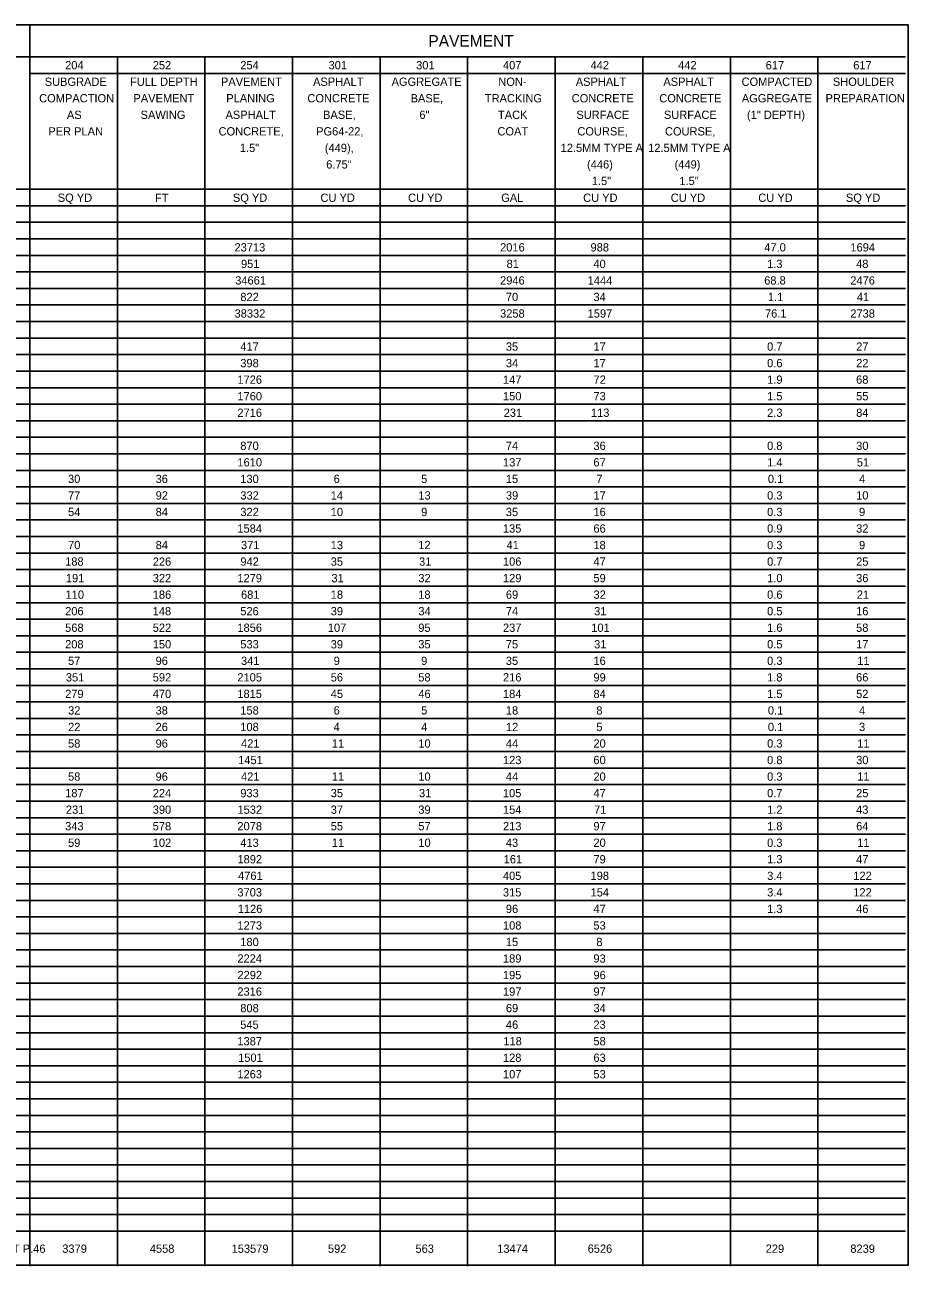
# Model space of a CAD drawing. Extents: x 12522 to 13018, y 1124 to 1902.
# Drawn here: x 12812.77 to 12827.72, y 1804.63 to 1825.65 of the extents above; entities that cross this region are included whole.
import ezdxf

# ---------------------------------------------------------------- set-up
doc = ezdxf.new("R2010")
doc.units = 0
for name, color, linetype in [('SC_Scratch1', 7, 'Continuous'), ('SH_Data', 7, 'Continuous'), ('SH_Text', 7, 'Continuous')]:
    doc.layers.add(name, color=color, linetype=linetype)

msp = doc.modelspace()

# ---------------------------------------------------------------- linework, layer by layer
at = {"layer": 'SC_Scratch1'}
msp.add_lwpolyline([(12797.224, 1825.65), (12827.724, 1825.65), (12827.724, 1804.65), (12797.224, 1804.65)], close=True, dxfattribs=at)
at = {"layer": 'SH_Data'}
for p, q in [((12812.855, 1825.65), (12812.855, 1804.634)), ((12797.224, 1825.107), (12827.678, 1825.107)), ((12814.337, 1825.107), (12814.337, 1804.634)), ((12815.82, 1825.107), (12815.82, 1804.634)), ((12817.302, 1825.107), (12817.302, 1804.634)), ((12818.784, 1825.107), (12818.784, 1804.634)), ((12820.267, 1825.107), (12820.267, 1804.634)), ((12821.749, 1825.107), (12821.749, 1804.634)), ((12823.231, 1825.107), (12823.231, 1804.634)), ((12824.714, 1825.107), (12824.714, 1804.634)), ((12826.196, 1825.107), (12826.196, 1804.634)), ((12812.855, 1824.827), (12827.678, 1824.827)), ((12806.184, 1822.867), (12827.678, 1822.867)), ((12797.224, 1822.587), (12827.678, 1822.587)), ((12797.224, 1822.307), (12827.678, 1822.307)), ((12797.224, 1822.027), (12827.678, 1822.027)), ((12797.224, 1821.747), (12827.678, 1821.747)), ((12797.224, 1821.467), (12827.678, 1821.467)), ((12797.224, 1821.187), (12827.678, 1821.187)), ((12797.224, 1820.907), (12827.678, 1820.907)), ((12797.224, 1820.627), (12827.678, 1820.627)), ((12797.224, 1820.347), (12827.678, 1820.347)), ((12797.224, 1820.067), (12827.678, 1820.067)), ((12797.224, 1819.787), (12827.678, 1819.787)), ((12797.224, 1819.507), (12827.678, 1819.507)), ((12797.224, 1819.227), (12827.678, 1819.227)), ((12797.224, 1818.947), (12827.678, 1818.947)), ((12797.224, 1818.667), (12827.678, 1818.667)), ((12797.224, 1818.387), (12827.678, 1818.387)), ((12797.224, 1818.107), (12827.678, 1818.107)), ((12797.224, 1817.827), (12827.678, 1817.827)), ((12797.224, 1817.547), (12827.678, 1817.547)), ((12797.224, 1817.267), (12827.678, 1817.267)), ((12797.224, 1816.987), (12827.678, 1816.987)), ((12797.224, 1816.707), (12827.678, 1816.707)), ((12797.224, 1816.427), (12827.678, 1816.427)), ((12797.224, 1816.147), (12827.678, 1816.147)), ((12797.224, 1815.867), (12827.678, 1815.867)), ((12797.224, 1815.587), (12827.678, 1815.587)), ((12797.224, 1815.307), (12827.678, 1815.307)), ((12797.224, 1815.027), (12827.678, 1815.027)), ((12797.224, 1814.747), (12827.678, 1814.747)), ((12797.224, 1814.467), (12827.678, 1814.467)), ((12797.224, 1814.187), (12827.678, 1814.187)), ((12797.224, 1813.907), (12827.678, 1813.907)), ((12797.224, 1813.627), (12827.678, 1813.627)), ((12797.224, 1813.347), (12827.678, 1813.347)), ((12797.224, 1813.067), (12827.678, 1813.067)), ((12797.224, 1812.787), (12827.678, 1812.787)), ((12797.224, 1812.507), (12827.678, 1812.507)), ((12797.224, 1812.227), (12827.678, 1812.227)), ((12797.224, 1811.947), (12827.678, 1811.947)), ((12797.224, 1811.667), (12827.678, 1811.667)), ((12797.224, 1811.387), (12827.678, 1811.387)), ((12797.224, 1811.107), (12827.678, 1811.107)), ((12797.224, 1810.827), (12827.678, 1810.827)), ((12797.224, 1810.547), (12827.678, 1810.547)), ((12797.224, 1810.267), (12827.678, 1810.267)), ((12797.224, 1809.987), (12827.678, 1809.987)), ((12797.224, 1809.707), (12827.678, 1809.707)), ((12797.224, 1809.427), (12827.678, 1809.427)), ((12797.224, 1809.147), (12827.678, 1809.147)), ((12797.224, 1808.867), (12827.678, 1808.867)), ((12797.224, 1808.587), (12827.678, 1808.587)), ((12797.224, 1808.307), (12827.678, 1808.307)), ((12797.224, 1808.027), (12827.678, 1808.027)), ((12797.224, 1807.747), (12827.678, 1807.747)), ((12797.224, 1807.467), (12827.678, 1807.467)), ((12797.224, 1807.187), (12827.678, 1807.187)), ((12797.224, 1806.907), (12827.678, 1806.907)), ((12797.224, 1806.627), (12827.678, 1806.627)), ((12797.224, 1806.347), (12827.678, 1806.347)), ((12797.224, 1806.067), (12827.678, 1806.067)), ((12797.224, 1805.787), (12827.678, 1805.787)), ((12797.224, 1805.507), (12827.678, 1805.507)), ((12797.224, 1805.227), (12827.678, 1805.227))]:
    msp.add_line(p, q, dxfattribs=at)

# ---------------------------------------------------------------- texts
at = {"layer": 'SH_Text'}
for s, height, p in [('PAVEMENT', 0.196, (12819.603, 1825.28)), ('204', 0.14, (12813.453, 1824.897)), ('252', 0.14, (12814.936, 1824.897)), ('254', 0.14, (12816.418, 1824.897)), ('301', 0.14, (12817.912, 1824.897)), ('301', 0.14, (12819.395, 1824.897)), ('407', 0.14, (12820.865, 1824.897)), ('442', 0.14, (12822.348, 1824.897)), ('442', 0.14, (12823.83, 1824.897)), ('617', 0.14, (12825.312, 1824.897)), ('617', 0.14, (12826.794, 1824.897)), ('SUBGRADE', 0.14, (12813.107, 1824.617)), ('FULL DEPTH', 0.14, (12814.551, 1824.617)), ('PAVEMENT', 0.14, (12816.091, 1824.617)), ('ASPHALT', 0.14, (12817.65, 1824.617)), ('AGGREGATE', 0.14, (12818.979, 1824.617)), ('NON-', 0.14, (12820.786, 1824.617)), ('ASPHALT', 0.14, (12822.097, 1824.617)), ('ASPHALT', 0.14, (12823.58, 1824.617)), ('COMPACTED', 0.14, (12824.904, 1824.617)), ('SHOULDER', 0.14, (12826.449, 1824.617)), ('COMPACTION', 0.14, (12813.013, 1824.337)), ('PAVEMENT', 0.14, (12814.609, 1824.337)), ('PLANING', 0.14, (12816.18, 1824.337)), ('CONCRETE', 0.14, (12817.554, 1824.337)), (' BASE,', 0.14, (12819.249, 1824.337)), ('TRACKING', 0.14, (12820.558, 1824.337)), (' CONCRETE', 0.14, (12821.976, 1824.337)), (' CONCRETE', 0.14, (12823.459, 1824.337)), ('AGGREGATE', 0.14, (12824.908, 1824.337)), ('PREPARATION', 0.14, (12826.326, 1824.337)), ('AS', 0.14, (12813.483, 1824.057)), ('SAWING', 0.14, (12814.73, 1824.057)), ('ASPHALT', 0.14, (12816.168, 1824.057)), (' BASE,', 0.14, (12817.767, 1824.057)), ('6"', 0.14, (12819.449, 1824.057)), ('TACK', 0.14, (12820.78, 1824.057)), (' SURFACE', 0.14, (12822.055, 1824.057)), (' SURFACE', 0.14, (12823.537, 1824.057)), ('(1" DEPTH)', 0.14, (12824.996, 1824.057)), ('PER PLAN', 0.14, (12813.168, 1823.777)), ('CONCRETE,', 0.14, (12816.05, 1823.777)), (' PG64-22,', 0.14, (12817.65, 1823.777)), ('COAT', 0.14, (12820.771, 1823.777)), (' COURSE,', 0.14, (12822.072, 1823.777)), (' COURSE,', 0.14, (12823.555, 1823.777)), ('1.5"', 0.14, (12816.411, 1823.497)), (' (449),', 0.14, (12817.797, 1823.497)), ('12.5MM TYPE A', 0.14, (12821.841, 1823.497)), ('12.5MM TYPE A', 0.14, (12823.323, 1823.497)), (' 6.75"', 0.14, (12817.82, 1823.217)), ('(446)', 0.14, (12822.288, 1823.217)), ('(449)', 0.14, (12823.77, 1823.217)), (' 1.5"', 0.14, (12822.316, 1822.937)), (' 1.5"', 0.14, (12823.799, 1822.937)), ('SQ YD', 0.14, (12813.328, 1822.653)), ('FT', 0.14, (12814.973, 1822.653)), ('SQ YD', 0.14, (12816.293, 1822.653)), ('CU YD', 0.14, (12817.775, 1822.653)), ('CU YD', 0.14, (12819.258, 1822.653)), ('GAL', 0.14, (12820.835, 1822.653)), ('CU YD', 0.14, (12822.222, 1822.653)), ('CU YD', 0.14, (12823.705, 1822.653)), ('CU YD', 0.14, (12825.187, 1822.653)), ('SQ YD', 0.14, (12826.67, 1822.653)), ('23713', 0.14, (12816.32, 1821.813)), ('2016', 0.14, (12820.816, 1821.813)), ('988', 0.14, (12822.347, 1821.813)), ('47.0', 0.14, (12825.288, 1821.813)), ('1694', 0.14, (12826.746, 1821.813)), ('951', 0.14, (12816.43, 1821.533)), ('81', 0.14, (12820.926, 1821.533)), ('40', 0.14, (12822.396, 1821.533)), ('1.3', 0.14, (12825.336, 1821.533)), ('48', 0.14, (12826.843, 1821.533)), ('34661', 0.14, (12816.332, 1821.253)), ('2946', 0.14, (12820.816, 1821.253)), ('1444', 0.14, (12822.299, 1821.253)), ('68.8', 0.14, (12825.287, 1821.253)), ('2476', 0.14, (12826.745, 1821.253)), ('822', 0.14, (12816.419, 1820.973)), ('70', 0.14, (12820.914, 1820.973)), ('34', 0.14, (12822.397, 1820.973)), ('1.1', 0.14, (12825.349, 1820.973)), ('41', 0.14, (12826.855, 1820.973)), ('38332', 0.14, (12816.321, 1820.693)), ('3258', 0.14, (12820.816, 1820.693)), ('1597', 0.14, (12822.298, 1820.693)), ('76.1', 0.14, (12825.3, 1820.693)), ('2738', 0.14, (12826.745, 1820.693)), ('417', 0.14, (12816.418, 1820.133)), ('35', 0.14, (12820.913, 1820.133)), ('17', 0.14, (12822.396, 1820.133)), ('0.7', 0.14, (12825.336, 1820.133)), ('27', 0.14, (12826.843, 1820.133)), ('398', 0.14, (12816.418, 1819.853)), ('34', 0.14, (12820.914, 1819.853)), ('17', 0.14, (12822.396, 1819.853)), ('0.6', 0.14, (12825.336, 1819.853)), ('22', 0.14, (12826.844, 1819.853)), ('1726', 0.14, (12816.369, 1819.573)), ('147', 0.14, (12820.865, 1819.573)), ('72', 0.14, (12822.397, 1819.573)), ('1.9', 0.14, (12825.336, 1819.573)), ('68', 0.14, (12826.843, 1819.573)), ('1760', 0.14, (12816.369, 1819.293)), ('150', 0.14, (12820.865, 1819.293)), ('73', 0.14, (12822.396, 1819.293)), ('1.5', 0.14, (12825.336, 1819.293)), ('55', 0.14, (12826.843, 1819.293)), ('2716', 0.14, (12816.369, 1819.013)), ('231', 0.14, (12820.877, 1819.013)), ('113', 0.14, (12822.354, 1819.013)), ('2.3', 0.14, (12825.336, 1819.013)), ('84', 0.14, (12826.844, 1819.013)), ('870', 0.14, (12816.418, 1818.453)), ('74', 0.14, (12820.914, 1818.453)), ('36', 0.14, (12822.396, 1818.453)), ('0.8', 0.14, (12825.336, 1818.453)), ('30', 0.14, (12826.844, 1818.453)), ('1610', 0.14, (12816.369, 1818.173)), ('137', 0.14, (12820.865, 1818.173)), ('67', 0.14, (12822.396, 1818.173)), ('1.4', 0.14, (12825.337, 1818.173)), ('51', 0.14, (12826.855, 1818.173)), ('30', 0.14, (12813.502, 1817.893)), ('36', 0.14, (12814.984, 1817.893)), ('130', 0.14, (12816.418, 1817.893)), ('6', 0.14, (12817.998, 1817.893)), ('5', 0.14, (12819.48, 1817.893)), ('15', 0.14, (12820.913, 1817.893)), ('7', 0.14, (12822.445, 1817.893)), ('0.1', 0.14, (12825.349, 1817.893)), ('4', 0.14, (12826.893, 1817.893)), ('77', 0.14, (12813.502, 1817.613)), ('92', 0.14, (12814.985, 1817.613)), ('332', 0.14, (12816.419, 1817.613)), ('14', 0.14, (12817.949, 1817.613)), ('13', 0.14, (12819.432, 1817.613)), ('39', 0.14, (12820.914, 1817.613)), ('17', 0.14, (12822.396, 1817.613)), ('0.3', 0.14, (12825.336, 1817.613)), ('10', 0.14, (12826.844, 1817.613)), ('54', 0.14, (12813.502, 1817.333)), ('84', 0.14, (12814.985, 1817.333)), ('322', 0.14, (12816.419, 1817.333)), ('10', 0.14, (12817.949, 1817.333)), ('9', 0.14, (12819.48, 1817.333)), ('35', 0.14, (12820.913, 1817.333)), ('16', 0.14, (12822.396, 1817.333)), ('0.3', 0.14, (12825.336, 1817.333)), ('9', 0.14, (12826.892, 1817.333)), ('1584', 0.14, (12816.369, 1817.053)), ('135', 0.14, (12820.864, 1817.053)), ('66', 0.14, (12822.396, 1817.053)), ('0.9', 0.14, (12825.336, 1817.053)), ('32', 0.14, (12826.844, 1817.053)), ('70', 0.14, (12813.502, 1816.773)), ('84', 0.14, (12814.985, 1816.773)), ('371', 0.14, (12816.43, 1816.773)), ('13', 0.14, (12817.949, 1816.773)), ('12', 0.14, (12819.432, 1816.773)), ('41', 0.14, (12820.926, 1816.773)), ('18', 0.14, (12822.396, 1816.773)), ('0.3', 0.14, (12825.336, 1816.773)), ('9', 0.14, (12826.892, 1816.773)), ('188', 0.14, (12813.453, 1816.493)), ('226', 0.14, (12814.936, 1816.493)), ('942', 0.14, (12816.419, 1816.493)), ('35', 0.14, (12817.949, 1816.493)), ('31', 0.14, (12819.444, 1816.493)), ('106', 0.14, (12820.865, 1816.493)), ('47', 0.14, (12822.396, 1816.493)), ('0.7', 0.14, (12825.336, 1816.493)), ('25', 0.14, (12826.843, 1816.493)), ('191', 0.14, (12813.465, 1816.213)), ('322', 0.14, (12814.936, 1816.213)), ('1279', 0.14, (12816.369, 1816.213)), ('31', 0.14, (12817.961, 1816.213)), ('32', 0.14, (12819.432, 1816.213)), ('129', 0.14, (12820.865, 1816.213)), ('59', 0.14, (12822.396, 1816.213)), ('1.0', 0.14, (12825.337, 1816.213)), ('36', 0.14, (12826.843, 1816.213)), ('110', 0.14, (12813.46, 1815.933)), ('186', 0.14, (12814.936, 1815.933)), ('681', 0.14, (12816.43, 1815.933)), ('18', 0.14, (12817.949, 1815.933)), ('18', 0.14, (12819.431, 1815.933)), ('69', 0.14, (12820.914, 1815.933)), ('32', 0.14, (12822.397, 1815.933)), ('0.6', 0.14, (12825.336, 1815.933)), ('21', 0.14, (12826.855, 1815.933)), ('206', 0.14, (12813.453, 1815.653)), ('148', 0.14, (12814.935, 1815.653)), ('526', 0.14, (12816.418, 1815.653)), ('39', 0.14, (12817.949, 1815.653)), ('34', 0.14, (12819.432, 1815.653)), ('74', 0.14, (12820.914, 1815.653)), ('31', 0.14, (12822.408, 1815.653)), ('0.5', 0.14, (12825.336, 1815.653)), ('16', 0.14, (12826.843, 1815.653)), ('568', 0.14, (12813.453, 1815.373)), ('522', 0.14, (12814.936, 1815.373)), ('1856', 0.14, (12816.369, 1815.373)), ('107', 0.14, (12817.9, 1815.373)), ('95', 0.14, (12819.431, 1815.373)), ('237', 0.14, (12820.865, 1815.373)), ('101', 0.14, (12822.359, 1815.373)), ('1.6', 0.14, (12825.336, 1815.373)), ('58', 0.14, (12826.843, 1815.373)), ('208', 0.14, (12813.453, 1815.093)), ('150', 0.14, (12814.936, 1815.093)), ('533', 0.14, (12816.418, 1815.093)), ('39', 0.14, (12817.949, 1815.093)), ('35', 0.14, (12819.431, 1815.093)), ('75', 0.14, (12820.913, 1815.093)), ('31', 0.14, (12822.408, 1815.093)), ('0.5', 0.14, (12825.336, 1815.093)), ('17', 0.14, (12826.843, 1815.093)), ('57', 0.14, (12813.502, 1814.813)), ('96', 0.14, (12814.984, 1814.813)), ('341', 0.14, (12816.43, 1814.813)), ('9', 0.14, (12817.998, 1814.813)), ('9', 0.14, (12819.48, 1814.813)), ('35', 0.14, (12820.913, 1814.813)), ('16', 0.14, (12822.396, 1814.813)), ('0.3', 0.14, (12825.336, 1814.813)), ('11', 0.14, (12826.862, 1814.813)), ('351', 0.14, (12813.465, 1814.533)), ('592', 0.14, (12814.936, 1814.533)), ('2105', 0.14, (12816.368, 1814.533)), ('56', 0.14, (12817.949, 1814.533)), ('58', 0.14, (12819.431, 1814.533)), ('216', 0.14, (12820.865, 1814.533)), ('99', 0.14, (12822.396, 1814.533)), ('1.8', 0.14, (12825.336, 1814.533)), ('66', 0.14, (12826.843, 1814.533)), ('279', 0.14, (12813.453, 1814.253)), ('470', 0.14, (12814.936, 1814.253)), ('1815', 0.14, (12816.368, 1814.253)), ('45', 0.14, (12817.949, 1814.253)), ('46', 0.14, (12819.432, 1814.253)), ('184', 0.14, (12820.865, 1814.253)), ('84', 0.14, (12822.397, 1814.253)), ('1.5', 0.14, (12825.336, 1814.253)), ('52', 0.14, (12826.844, 1814.253)), ('32', 0.14, (12813.503, 1813.973)), ('38', 0.14, (12814.984, 1813.973)), ('158', 0.14, (12816.418, 1813.973)), ('6', 0.14, (12817.998, 1813.973)), ('5', 0.14, (12819.48, 1813.973)), ('18', 0.14, (12820.914, 1813.973)), ('8', 0.14, (12822.445, 1813.973)), ('0.1', 0.14, (12825.349, 1813.973)), ('4', 0.14, (12826.893, 1813.973)), ('22', 0.14, (12813.503, 1813.693)), ('26', 0.14, (12814.984, 1813.693)), ('108', 0.14, (12816.418, 1813.693)), ('4', 0.14, (12817.998, 1813.693)), ('4', 0.14, (12819.481, 1813.693)), ('12', 0.14, (12820.915, 1813.693)), ('5', 0.14, (12822.445, 1813.693)), ('0.1', 0.14, (12825.349, 1813.693)), ('3', 0.14, (12826.892, 1813.693)), ('58', 0.14, (12813.502, 1813.413)), ('96', 0.14, (12814.984, 1813.413)), ('421', 0.14, (12816.43, 1813.413)), ('11', 0.14, (12817.968, 1813.413)), ('10', 0.14, (12819.432, 1813.413)), ('44', 0.14, (12820.914, 1813.413)), ('20', 0.14, (12822.396, 1813.413)), ('0.3', 0.14, (12825.336, 1813.413)), ('11', 0.14, (12826.862, 1813.413)), ('1451', 0.14, (12816.381, 1813.133)), ('123', 0.14, (12820.865, 1813.133)), ('60', 0.14, (12822.396, 1813.133)), ('0.8', 0.14, (12825.336, 1813.133)), ('30', 0.14, (12826.844, 1813.133)), ('58', 0.14, (12813.502, 1812.853)), ('96', 0.14, (12814.984, 1812.853)), ('421', 0.14, (12816.43, 1812.853)), ('11', 0.14, (12817.968, 1812.853)), ('10', 0.14, (12819.432, 1812.853)), ('44', 0.14, (12820.914, 1812.853)), ('20', 0.14, (12822.396, 1812.853)), ('0.3', 0.14, (12825.336, 1812.853)), ('11', 0.14, (12826.862, 1812.853)), ('187', 0.14, (12813.453, 1812.573)), ('224', 0.14, (12814.936, 1812.573)), ('933', 0.14, (12816.418, 1812.573)), ('35', 0.14, (12817.949, 1812.573)), ('31', 0.14, (12819.444, 1812.573)), ('105', 0.14, (12820.864, 1812.573)), ('47', 0.14, (12822.396, 1812.573)), ('0.7', 0.14, (12825.336, 1812.573)), ('25', 0.14, (12826.843, 1812.573)), ('231', 0.14, (12813.465, 1812.293)), ('390', 0.14, (12814.936, 1812.293)), ('1532', 0.14, (12816.37, 1812.293)), ('37', 0.14, (12817.949, 1812.293)), ('39', 0.14, (12819.431, 1812.293)), ('154', 0.14, (12820.865, 1812.293)), ('71', 0.14, (12822.408, 1812.293)), ('1.2', 0.14, (12825.337, 1812.293)), ('43', 0.14, (12826.843, 1812.293)), ('343', 0.14, (12813.453, 1812.013)), ('578', 0.14, (12814.935, 1812.013)), ('2078', 0.14, (12816.369, 1812.013)), ('55', 0.14, (12817.949, 1812.013)), ('57', 0.14, (12819.432, 1812.013)), ('213', 0.14, (12820.865, 1812.013)), ('97', 0.14, (12822.396, 1812.013)), ('1.8', 0.14, (12825.336, 1812.013)), ('64', 0.14, (12826.844, 1812.013)), ('59', 0.14, (12813.502, 1811.733)), ('102', 0.14, (12814.936, 1811.733)), ('413', 0.14, (12816.418, 1811.733)), ('11', 0.14, (12817.968, 1811.733)), ('10', 0.14, (12819.432, 1811.733)), ('43', 0.14, (12820.914, 1811.733)), ('20', 0.14, (12822.396, 1811.733)), ('0.3', 0.14, (12825.336, 1811.733)), ('11', 0.14, (12826.862, 1811.733)), ('1892', 0.14, (12816.37, 1811.453)), ('161', 0.14, (12820.877, 1811.453)), ('79', 0.14, (12822.396, 1811.453)), ('1.3', 0.14, (12825.336, 1811.453)), ('47', 0.14, (12826.843, 1811.453)), ('4761', 0.14, (12816.381, 1811.173)), ('405', 0.14, (12820.864, 1811.173)), ('198', 0.14, (12822.347, 1811.173)), ('3.4', 0.14, (12825.337, 1811.173)), ('122', 0.14, (12826.795, 1811.173)), ('3703', 0.14, (12816.369, 1810.893)), ('315', 0.14, (12820.864, 1810.893)), ('154', 0.14, (12822.348, 1810.893)), ('3.4', 0.14, (12825.337, 1810.893)), ('122', 0.14, (12826.795, 1810.893)), ('1126', 0.14, (12816.375, 1810.613)), ('96', 0.14, (12820.914, 1810.613)), ('47', 0.14, (12822.396, 1810.613)), ('1.3', 0.14, (12825.336, 1810.613)), ('46', 0.14, (12826.843, 1810.613)), ('1273', 0.14, (12816.369, 1810.333)), ('108', 0.14, (12820.865, 1810.333)), ('53', 0.14, (12822.396, 1810.333)), ('180', 0.14, (12816.418, 1810.053)), ('15', 0.14, (12820.913, 1810.053)), ('8', 0.14, (12822.445, 1810.053)), ('2224', 0.14, (12816.369, 1809.773)), ('189', 0.14, (12820.865, 1809.773)), ('93', 0.14, (12822.396, 1809.773)), ('2292', 0.14, (12816.37, 1809.493)), ('195', 0.14, (12820.864, 1809.493)), ('96', 0.14, (12822.396, 1809.493)), ('2316', 0.14, (12816.369, 1809.213)), ('197', 0.14, (12820.865, 1809.213)), ('97', 0.14, (12822.396, 1809.213)), ('808', 0.14, (12816.418, 1808.933)), ('69', 0.14, (12820.914, 1808.933)), ('34', 0.14, (12822.397, 1808.933)), ('545', 0.14, (12816.417, 1808.653)), ('46', 0.14, (12820.914, 1808.653)), ('23', 0.14, (12822.396, 1808.653)), ('1387', 0.14, (12816.369, 1808.373)), ('118', 0.14, (12820.871, 1808.373)), ('58', 0.14, (12822.396, 1808.373)), ('1501', 0.14, (12816.381, 1808.093)), ('128', 0.14, (12820.865, 1808.093)), ('63', 0.14, (12822.396, 1808.093)), ('1263', 0.14, (12816.369, 1807.813)), ('107', 0.14, (12820.865, 1807.813)), ('53', 0.14, (12822.396, 1807.813)), ('TOTALS CARRIED TO PAVEMENT SUBSUMMARY SHEET P.46', 0.14, (12807.597, 1804.86)), ('3379', 0.14, (12813.404, 1804.86)), ('4558', 0.14, (12814.886, 1804.86)), ('153579', 0.14, (12816.271, 1804.86)), ('592', 0.14, (12817.901, 1804.86)), ('563', 0.14, (12819.383, 1804.86)), ('13474', 0.14, (12820.767, 1804.86)), ('6526', 0.14, (12822.298, 1804.86)), ('229', 0.14, (12825.312, 1804.86)), ('8239', 0.14, (12826.745, 1804.86))]:
    msp.add_text(s, height=height, dxfattribs=at).set_placement(p)

doc.saveas('drawing.dxf')
